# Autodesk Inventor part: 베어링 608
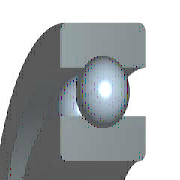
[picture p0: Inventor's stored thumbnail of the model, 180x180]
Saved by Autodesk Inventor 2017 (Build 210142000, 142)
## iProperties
IsCustomPart: 1
Created: 2012-02
Part Number: 베어링 608
Material: 강철, 연강
Description: 깊은 그루브 볼 베어링
Document SubType Name: Modeling
Standard: KS B 2023
Designer: mduedu
Standards Organization: KS
Language: ko-KR
Size Designation: 608 - 8 x 22 x 7
Categories: <MemberInstance><Categories><Category DisplayName="샤프트 부품" InternalName="7f7aeb1f-a693-4053-b835-cee3144e0d98" Mnemonic="SHFT"><Category DisplayName="베어링" Inter
Density: 1 g/cm^3
Appearance: 주황색
Author: mduedu
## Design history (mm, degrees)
sketch "스케치" dims "d0" = 3.64 (= -0.26 x WD + 0.26 x BD)
  geometry: L1 (1.68, 7.5)-(5.32, 7.5); L2 (3.5, 7.5)-(3.5, 5.68); L3 (3.5, 7.5)-(3.5, 9.32); L4 (2.148, 6.282)-(0, 6.282); L5 (0, 4)-(7, 4); L6 (2.148, 8.718)-(0, 8.718); L7 (0, 11)-(7, 11); L8 (7, 4)-(7, 6.282); L9 (4.852, 6.282)-(7, 6.282); L10 (4.852, 8.718)-(7, 8.718); L11 (7, 11)-(7, 8.718); L12 (-1.4, 0)-(8.4, 0) reference; L13 (0, -0.3)-(0, 5.3) reference
  constraints: 22 end point, 4 point on line, 2 collinear, 2 perpendicular, 2 symmetric about line, 1 midpoint, 1 parallel, 14 other
  dimensions: "d9" = 8 diameter of L5 L12 (= WD); "d11" = 22 diameter of L7 L12 (= BD); "d12" = 7 distance between parallel lines of L8 L13 (= KB); "d13" = 12.564 diameter of L9 L12 (= 0.326 x BD + 0.674 x WD)
revolve "본체" stored, may be unused: angle "d6" = 90 deg
revolve "볼" stored, may be unused: angle "d7" = 90 deg
pattern_circular "IDS_ARRAYBALL[SIMPL:T]" dims angle "d3" = 360 deg
body "Solid1"
fillet "모깎기1" dims "d1" = 0.3 (= KRS)
other parameters: "WD" = 8 [user parameter; used in 5 equation terms], "BD" = 22 [user parameter; used in 5 equation terms], "KB" = 7 [user parameter; used in 1 equation term], "KRS" = 0.3 [user parameter; used in 1 equation term], "d4" = 0, "d5" = 0, "d8" = 0, "d14" = 0, "d15" = 0, "BBA" = 0 [user parameter], "BC0" = 1370000 [user parameter], "BC" = 3250000 [user parameter], "BR" = 11 (= 0.5 x BD) [user parameter], "WR" = 4 (= 0.5 x WD) [user parameter]
